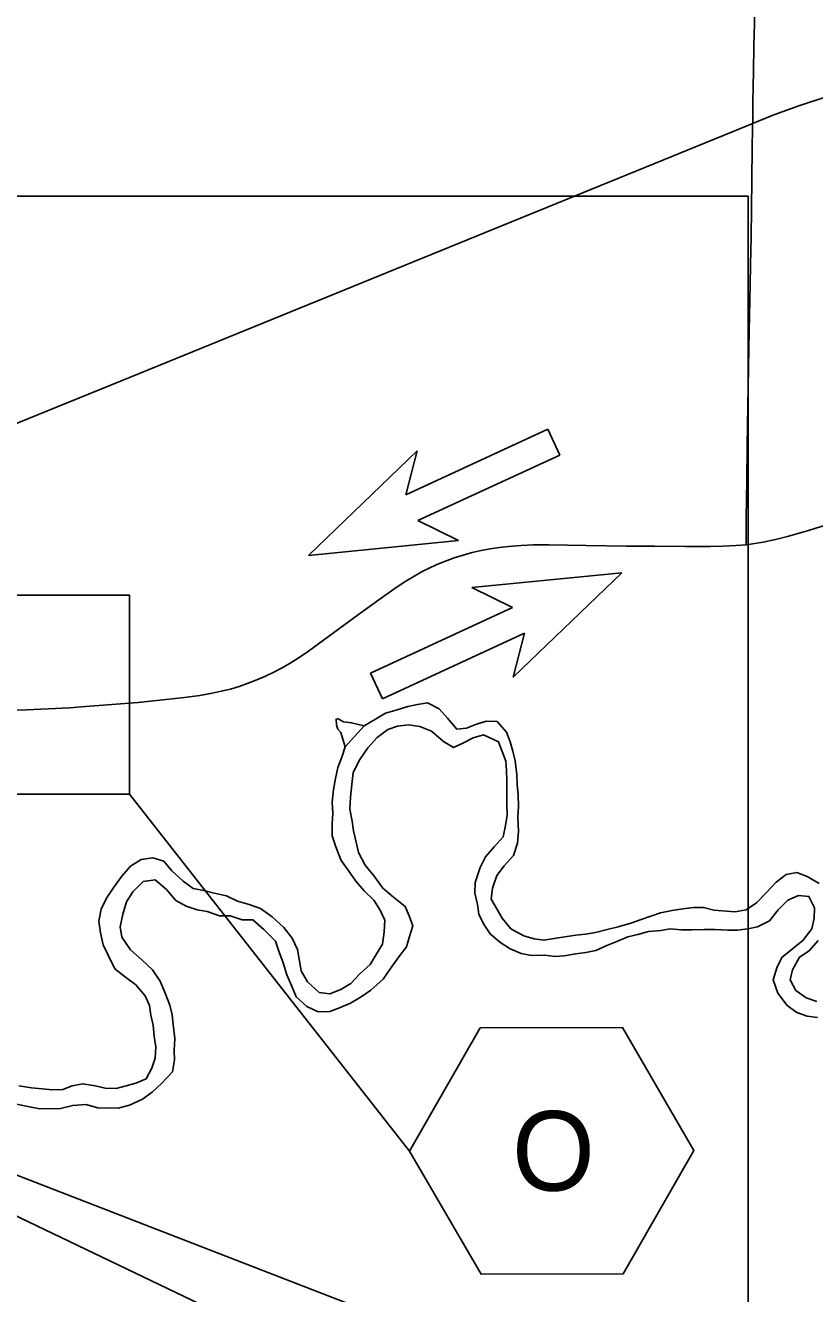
# Model space of a CAD drawing. Extents: x 0 to 680, y 0 to 440.
# Drawn here: x 100.85 to 128.6, y 357.34 to 401.95 of the extents above; entities that cross this region are included whole.
import ezdxf

# ---------------------------------------------------------------- set-up
doc = ezdxf.new("R2010")
doc.units = 0
for name, color, linetype in [('GM_X_Major_River', 7, 'Continuous'), ('GM_X_State_Route', 7, 'Continuous'), ('GM_X_Township_Road', 7, 'Continuous'), ('PM_P_Cells', 7, 'Continuous'), ('RD_X_RR_2', 7, 'Continuous'), ('SH_Border', 7, 'Continuous'), ('SH_Text', 7, 'Continuous')]:
    doc.layers.add(name, color=color, linetype=linetype)

msp = doc.modelspace()

# ---------------------------------------------------------------- linework, layer by layer
at = {"layer": 'GM_X_Major_River'}
for points in [[(128.754, 371.759), (128.331, 372.007), (127.973, 372.147), (127.598, 372.086), (127.246, 371.811), (126.906, 371.442), (126.554, 371.087), (126.189, 370.839), (125.801, 370.766), (125.054, 370.831), (124.695, 370.918), (124.335, 370.923), (123.96, 370.876), (123.586, 370.816), (123.184, 370.729), (122.835, 370.614), (122.499, 370.499), (122.137, 370.372), (121.694, 370.245), (121.305, 370.145), (120.89, 370.045), (120.542, 369.984), (120.208, 369.949), (119.819, 369.889), (119.445, 369.828), (119.083, 369.767), (118.737, 369.813), (118.378, 369.926), (117.915, 370.174), (117.614, 370.54), (117.419, 370.877), (117.225, 371.215), (117.271, 371.602), (117.425, 372.04), (117.684, 372.383), (118.011, 372.752), (118.151, 373.178), (118.184, 373.591), (118.166, 374.1), (118.185, 374.474), (118.179, 374.888), (118.145, 375.249), (118.124, 375.597), (118.065, 376.079), (117.99, 376.415), (117.889, 376.751), (117.761, 377.087), (117.433, 377.466), (117.06, 377.473), (116.711, 377.371), (116.362, 377.23), (116.014, 377.196), (115.687, 377.575), (115.398, 377.914), (114.988, 378.122), (114.64, 378.061), (114.292, 377.986), (113.916, 377.872), (113.514, 377.758), (113.163, 377.55), (112.759, 377.316)], [(112.759, 377.316), (112.32, 377.417), (112.04, 377.449), (111.842, 377.559), (111.775, 377.547), (111.785, 377.346), (111.81, 377.265), (111.836, 377.198), (111.941, 377.076), (112.092, 376.566)], [(101.362, 363.838), (102.087, 363.846), (102.516, 363.959), (102.97, 363.991), (103.396, 363.877), (104.116, 363.866), (104.505, 363.966), (104.962, 364.172), (105.313, 364.421), (105.652, 364.736), (106.019, 365.144), (106.093, 365.557), (106.085, 365.892), (106.105, 366.306), (106.046, 366.801), (106.012, 367.149), (105.924, 367.485), (105.77, 367.902), (105.591, 368.333), (105.317, 368.725), (104.949, 369.078), (104.541, 369.433), (104.241, 369.879), (104.18, 370.24), (104.281, 370.68), (104.408, 371.119), (104.627, 371.476), (104.994, 371.831), (105.408, 371.891), (105.817, 371.55), (106.144, 371.17), (106.501, 370.964), (106.886, 370.837), (107.246, 370.778), (107.67, 370.624), (108.044, 370.631), (108.469, 370.49), (108.843, 370.484), (109.238, 370.144), (109.645, 369.736), (109.759, 369.386), (109.913, 368.97), (110.039, 368.553), (110.207, 368.176), (110.374, 367.772), (110.742, 367.432), (111.14, 367.252), (111.553, 367.258), (111.889, 367.386), (112.279, 367.554), (112.656, 367.775), (112.994, 368.01), (113.428, 368.404), (113.687, 368.774), (113.974, 369.183), (114.247, 369.54), (114.36, 369.899), (114.473, 370.271), (114.345, 370.621), (114.203, 370.957), (113.795, 371.285), (113.413, 371.598), (113.113, 372.018), (112.799, 372.411), (112.566, 372.855), (112.478, 373.218), (112.391, 373.62), (112.343, 373.955), (112.257, 374.384), (112.277, 374.798), (112.325, 375.252), (112.371, 375.665), (112.606, 376.129), (112.893, 376.539), (113.219, 376.895), (113.598, 377.182), (113.933, 377.297), (114.321, 377.344), (114.721, 377.284), (115.132, 377.117), (115.553, 376.762), (115.897, 376.543), (116.233, 376.698), (116.596, 376.892), (116.959, 376.993), (117.488, 376.744), (117.744, 376.071), (117.766, 375.737), (117.773, 375.389), (117.779, 374.908), (117.773, 374.56), (117.793, 374.173), (117.734, 373.799), (117.647, 373.4), (117.335, 373.057), (117.022, 372.702), (116.842, 372.33), (116.66, 371.799), (116.654, 371.425), (116.741, 371.022), (116.789, 370.687)], [(112.092, 376.566), (112.759, 377.316)], [(112.092, 376.566), (111.98, 376.207), (111.84, 375.848), (111.754, 375.462), (111.681, 375.075), (111.633, 374.622), (111.654, 374.234), (111.634, 373.86), (111.641, 373.445), (111.768, 373.056), (111.947, 372.572), (112.195, 372.233), (112.469, 371.841), (112.757, 371.502), (113.099, 371.176), (113.32, 370.825), (113.488, 370.474), (113.468, 370.06), (113.408, 369.634), (113.188, 369.263), (112.969, 368.919), (112.603, 368.591), (112.29, 368.249), (111.94, 368.041), (111.55, 367.887), (111.177, 367.933), (110.769, 368.301), (110.549, 368.692), (110.488, 369.027), (110.414, 369.443), (110.234, 369.846), (109.933, 370.212), (109.525, 370.593), (109.116, 370.881), (108.718, 371.021), (108.306, 371.148), (107.922, 371.328), (107.483, 371.429), (107.124, 371.515), (106.752, 371.588), (106.395, 371.848), (106.001, 372.215), (105.713, 372.554), (105.328, 372.668), (104.926, 372.607), (104.548, 372.373), (104.236, 372.017), (103.935, 371.595), (103.703, 371.251), (103.509, 370.866), (103.436, 370.44), (103.496, 370.025), (103.582, 369.609), (103.763, 369.245), (103.996, 368.76), (104.365, 368.473), (104.734, 368.2), (105.061, 367.807), (105.216, 367.47), (105.264, 367.135), (105.338, 366.786), (105.372, 366.398), (105.433, 366.023), (105.413, 365.622), (105.3, 365.263), (105.094, 364.892), (104.731, 364.738), (104.396, 364.65), (104.047, 364.548), (103.66, 364.568), (103.301, 364.641), (102.875, 364.715), (102.5, 364.641), (102.164, 364.513), (101.817, 364.505)], [(116.789, 370.687), (116.957, 370.35), (117.191, 369.999), (117.534, 369.699), (117.89, 369.466), (118.275, 369.299), (118.647, 369.226), (119.115, 369.245), (119.461, 369.2), (119.795, 369.221), (120.197, 369.294), (120.558, 369.342), (120.906, 369.403), (121.296, 369.584), (121.646, 369.725), (122.035, 369.892), (122.384, 369.967), (122.759, 370.081), (123.187, 370.114), (123.522, 370.175), (123.908, 370.129), (124.295, 370.136), (124.709, 370.142), (125.097, 370.149), (125.55, 370.128), (125.884, 370.123), (126.245, 370.17), (126.593, 370.245), (127.01, 370.452), (127.31, 370.834), (127.65, 371.176), (128.026, 371.344), (128.399, 371.311), (128.593, 370.907), (128.587, 370.546), (128.501, 370.173), (128.187, 369.764), (127.822, 369.462), (127.457, 369.174), (127.278, 368.83), (127.137, 368.378), (127.303, 367.907), (127.629, 367.474), (127.972, 367.228), (128.331, 367.102), (128.704, 367.055)], [(128.673, 367.617), (128.301, 367.744), (127.932, 368.004), (127.738, 368.381), (127.823, 368.727), (128.071, 369.178), (128.408, 369.399), (128.721, 369.755)], [(101.817, 364.505), (101.062, 364.575), (100.623, 364.646)], [(100.538, 364.005), (100.937, 363.921), (101.362, 363.838)]]:
    msp.add_lwpolyline(points, dxfattribs=at)
at = {"layer": 'GM_X_State_Route'}
msp.add_line((114.356, 362.344), (104.509, 374.91), dxfattribs=at)
msp.add_lwpolyline([(100.328, 377.864), (100.887, 377.879), (102.413, 377.949), (102.959, 377.985), (104.81, 378.137), (105.68, 378.222), (106.441, 378.308), (106.983, 378.383), (107.415, 378.457), (107.737, 378.525), (108.056, 378.605), (108.371, 378.699), (108.682, 378.808), (108.988, 378.928), (109.29, 379.059), (109.586, 379.203), (109.877, 379.356), (110.162, 379.519), (110.441, 379.694), (110.802, 379.941), (111.687, 380.582), (112.566, 381.231), (113.272, 381.746), (113.808, 382.121), (114.172, 382.362), (114.543, 382.589), (114.827, 382.75), (115.021, 382.849), (115.317, 382.984), (115.62, 383.105), (115.928, 383.215), (116.238, 383.316), (116.553, 383.403), (116.871, 383.477), (117.191, 383.539), (117.514, 383.587), (117.838, 383.622), (118.273, 383.654), (118.708, 383.672), (119.254, 383.677), (120.564, 383.655), (121.984, 383.635), (122.967, 383.627), (124.059, 383.615), (124.934, 383.614), (125.372, 383.63), (125.822, 383.653), (126.195, 383.683), (126.791, 383.775), (127.222, 383.86), (127.648, 383.967), (128.385, 384.18), (130.471, 384.843)], dxfattribs=at)
msp.add_lwpolyline([(121.842, 366.697), (116.842, 366.682), (114.356, 362.344), (116.87, 358.021), (121.87, 358.037), (124.356, 362.375)], close=True, dxfattribs=at)
at = {"layer": 'GM_X_Township_Road'}
for points in [[(126.465, 401.269), (126.481, 402.005), (126.478, 402.334), (126.534, 405.397), (126.547, 406.491), (126.565, 407.475), (126.598, 409.116), (126.625, 410.428), (126.638, 411.522), (126.642, 411.767)], [(126.195, 383.683), (126.191, 384.191), (126.193, 384.62), (126.211, 385.94), (126.227, 387.142), (126.24, 387.891), (126.262, 389.219), (126.283, 390.601), (126.294, 391.195), (126.335, 392.836), (126.347, 393.53), (126.363, 394.515), (126.377, 395.509), (126.391, 396.516), (126.407, 397.655), (126.417, 398.312), (126.421, 398.64), (126.426, 399.187), (126.434, 399.844), (126.443, 400.282), (126.465, 401.269)]]:
    msp.add_lwpolyline(points, dxfattribs=at)
at = {"layer": 'PM_P_Cells'}
for p, q in [((114.23, 385.439), (119.223, 387.745)), ((119.223, 387.745), (119.642, 386.837)), ((119.433, 387.291), (119.433, 387.291)), ((110.808, 383.307), (114.619, 386.98)), ((114.619, 386.98), (114.23, 385.439)), ((119.642, 386.837), (114.649, 384.531)), ((114.649, 384.531), (116.075, 383.828)), ((116.075, 383.828), (110.808, 383.307)), ((110.808, 383.307), (110.808, 383.307)), ((116.548, 382.177), (121.815, 382.698)), ((121.815, 382.698), (118.004, 379.025)), ((121.815, 382.698), (121.815, 382.698)), ((117.974, 381.474), (116.548, 382.177)), ((112.981, 379.168), (117.974, 381.474)), ((118.393, 380.566), (113.4, 378.26)), ((118.004, 379.025), (118.393, 380.566)), ((113.4, 378.26), (112.981, 379.168)), ((113.19, 378.714), (113.19, 378.714))]:
    msp.add_line(p, q, dxfattribs=at)
at = {"layer": 'RD_X_RR_2'}
msp.add_lwpolyline([(199.793, 400.863), (177.185, 401.052), (155.889, 401.213), (145.782, 401.292), (141.073, 401.319), (139.985, 401.315), (139.094, 401.284), (138.072, 401.225), (136.914, 401.131), (136.061, 401.036), (135.323, 400.926), (134.314, 400.769), (133.284, 400.577), (132.35, 400.376), (131.116, 400.078), (129.993, 399.756), (129.07, 399.461), (128.045, 399.12), (127.161, 398.802), (125.417, 398.093), (104.891, 389.716), (80.55, 379.817), (63.347, 372.766), (30, 359.107)], dxfattribs=at)
at = {"layer": 'SH_Border'}
msp.add_lwpolyline([(96.884, 381.91), (104.509, 381.91), (104.509, 374.91), (96.884, 374.91)], close=True, dxfattribs=at)
at = {"layer": 'SH_Text'}
for points in [[(48.072, 395.938), (126.265, 395.938), (126.265, 313.95), (48.072, 313.95)], [(133.772, 344.117), (84.828, 367.603), (133.772, 348.612)]]:
    msp.add_lwpolyline(points, close=True, dxfattribs=at)

# ---------------------------------------------------------------- texts
at = {"layer": 'GM_X_State_Route'}
msp.add_text('O', height=2.8, dxfattribs=at).set_placement((117.959, 360.959))

doc.saveas('drawing.dxf')
